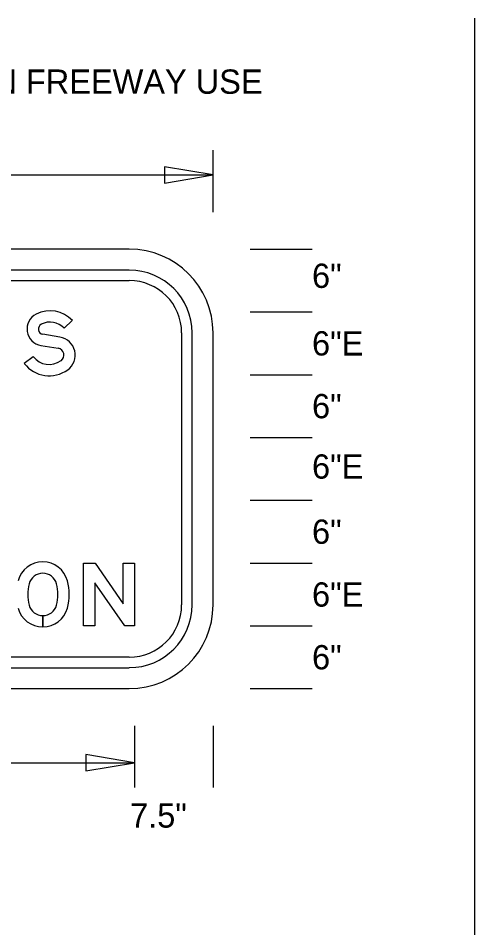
# Model space of a CAD drawing. Extents: x 0 to 770, y 0 to 495.
# Drawn here: x 319.6 to 385.3, y 363.9 to 495 of the extents above; entities that cross this region are included whole.
import ezdxf

# ---------------------------------------------------------------- set-up
doc = ezdxf.new("R2010")
doc.units = 0
for name, color, linetype in [('Dimension', 7, 'Continuous'), ('GSBWFill', 7, 'Continuous'), ('GSColorFill', 7, 'Continuous'), ('GSDims', 7, 'Continuous'), ('GSOutline', 7, 'Continuous'), ('SheetLines_dp', 7, 'Continuous'), ('TextStructures', 7, 'Continuous')]:
    doc.layers.add(name, color=color, linetype=linetype)

msp = doc.modelspace()

# ---------------------------------------------------------------- linework, layer by layer
at = {"layer": 'Dimension'}
for points in [[(347.62, 472.41), (340.61, 473.59), (340.61, 471.22)], [(336.32, 387.73), (329.3, 388.91), (329.3, 386.54)]]:
    msp.add_lwpolyline(points, close=True, dxfattribs=at)
at = {"layer": 'GSBWFill'}
for p, q in [((335.56, 461.72), (233.06, 461.72)), ((335.56, 458.71), (233.06, 458.71)), ((233.06, 457.2), (335.56, 457.2)), ((326.17, 450.33), (327.36, 451.43)), ((343.1, 449.66), (343.1, 410.47)), ((344.61, 410.47), (344.61, 449.66)), ((347.62, 410.47), (347.62, 449.66)), ((325.58, 449.05), (323.12, 449.46)), ((322.85, 447.86), (325.31, 447.44)), ((321.73, 446.23), (320.44, 445.24)), ((323.11, 407.3), (323.11, 408.92)), ((323.11, 408.92), (323.11, 407.3)), ((335.56, 402.93), (233.07, 402.93)), ((233.07, 401.42), (335.56, 401.42)), ((233.06, 398.41), (335.56, 398.41))]:
    msp.add_line(p, q, dxfattribs=at)
msp.add_lwpolyline([(336.32, 416.5), (336.32, 407.45), (334.92, 407.45), (330.62, 413.65), (330.62, 407.45), (328.99, 407.45), (328.99, 416.5), (330.63, 416.5), (334.69, 410.64), (334.69, 416.5)], close=True, dxfattribs=at)
for centre, radius, start, end in [((335.56, 449.66), 12.06, 0, 90), ((335.56, 449.66), 9.04, 0, 90), ((335.56, 449.66), 7.54, 0, 90), ((323.25, 450.22), 2.4, 116.9123, 260.4087), ((324.15, 448.45), 4.39, 42.8759, 116.9123), ((323.25, 450.22), 0.769, 116.9123, 260.4087), ((324.15, 448.45), 2.76, 42.8759, 116.9123), ((325.15, 446.46), 2.62, 306.123, 80.4087), ((325.15, 446.46), 0.995, 306.123, 80.4087), ((324.03, 448), 2.89, 217.5895, 306.123), ((324.03, 448), 4.52, 217.5895, 306.123), ((335.56, 410.47), 9.04, 270, 0), ((335.56, 410.47), 7.54, 270, 0), ((335.56, 410.47), 12.06, 270, 0)]:
    msp.add_arc(centre, radius, start, end, dxfattribs=at)
for centre, major_axis, start_param, end_param in [((323.11, 412.99), (0, 3.67), 4.973521, 7.592849), ((323.11, 412.99), (0, 2.04), 4.973521, 7.592849), ((326.91, 411.98), (0, 5.97), 1.309664, 1.831929), ((319.31, 411.98), (0, 5.97), 4.451257, 4.973521), ((319.31, 411.98), (0, 7.6), 4.451257, 4.973521), ((323.11, 410.96), (0, 2.04), 1.831929, 3.141593), ((323.11, 410.96), (0, 2.04), 3.141815, 4.451257), ((323.11, 410.96), (0, 3.67), 1.831929, 3.141593), ((323.11, 410.96), (0, 3.67), 3.141716, 4.451257)]:
    msp.add_ellipse(centre, major_axis=major_axis, ratio=0.999994, start_param=start_param, end_param=end_param, dxfattribs=at)
at = {"layer": 'GSColorFill'}
for p, q in [((326.17, 450.33), (327.36, 451.43)), ((325.58, 449.05), (323.12, 449.46)), ((322.85, 447.86), (325.31, 447.44)), ((321.73, 446.23), (320.44, 445.24)), ((323.11, 407.3), (323.11, 408.92)), ((323.11, 408.92), (323.11, 407.3))]:
    msp.add_line(p, q, dxfattribs=at)
msp.add_lwpolyline([(336.32, 416.5), (336.32, 407.45), (334.92, 407.45), (330.62, 413.65), (330.62, 407.45), (328.99, 407.45), (328.99, 416.5), (330.63, 416.5), (334.69, 410.64), (334.69, 416.5)], close=True, dxfattribs=at)
for centre, radius, start, end in [((323.25, 450.22), 2.4, 116.9123, 260.4087), ((324.15, 448.45), 4.39, 42.8759, 116.9123), ((323.25, 450.22), 0.769, 116.9123, 260.4087), ((324.15, 448.45), 2.76, 42.8759, 116.9123), ((325.15, 446.46), 2.62, 306.123, 80.4087), ((325.15, 446.46), 0.995, 306.123, 80.4087), ((324.03, 448), 2.89, 217.5895, 306.123), ((324.03, 448), 4.52, 217.5895, 306.123)]:
    msp.add_arc(centre, radius, start, end, dxfattribs=at)
for centre, major_axis, start_param, end_param in [((323.11, 412.99), (0, 3.67), 4.973521, 7.592849), ((323.11, 412.99), (0, 2.04), 4.973521, 7.592849), ((326.91, 411.98), (0, 5.97), 1.309664, 1.831929), ((319.31, 411.98), (0, 5.97), 4.451257, 4.973521), ((319.31, 411.98), (0, 7.6), 4.451257, 4.973521), ((323.11, 410.96), (0, 2.04), 1.831929, 3.141593), ((323.11, 410.96), (0, 2.04), 3.141815, 4.451257), ((323.11, 410.96), (0, 3.67), 1.831929, 3.141593), ((323.11, 410.96), (0, 3.67), 3.141716, 4.451257)]:
    msp.add_ellipse(centre, major_axis=major_axis, ratio=0.999994, start_param=start_param, end_param=end_param, dxfattribs=at)
at = {"layer": 'GSDims'}
for p, q in [((347.62, 467.06), (347.62, 475.97)), ((221, 472.41), (347.62, 472.41)), ((352.97, 461.72), (361.87, 461.72)), ((352.97, 452.68), (361.87, 452.68)), ((352.97, 452.68), (361.87, 452.68)), ((352.97, 443.63), (361.87, 443.63)), ((352.97, 443.63), (361.87, 443.63)), ((352.97, 434.59), (361.87, 434.59)), ((352.97, 434.59), (361.87, 434.59)), ((352.97, 425.54), (361.87, 425.54)), ((352.97, 425.54), (361.87, 425.54)), ((352.97, 416.5), (361.87, 416.5)), ((352.97, 416.5), (361.87, 416.5)), ((352.97, 407.45), (361.87, 407.45)), ((352.97, 407.45), (361.87, 407.45)), ((352.97, 398.41), (361.87, 398.41)), ((336.32, 393.07), (336.32, 384.16)), ((336.32, 393.07), (336.32, 384.16)), ((347.62, 393.07), (347.62, 384.16)), ((232.31, 387.73), (336.32, 387.73))]:
    msp.add_line(p, q, dxfattribs=at)
at = {"layer": 'GSOutline'}
for p, q in [((326.17, 450.33), (327.36, 451.43)), ((325.58, 449.05), (323.12, 449.46)), ((322.85, 447.86), (325.31, 447.44)), ((321.73, 446.23), (320.44, 445.24))]:
    msp.add_line(p, q, dxfattribs=at)
msp.add_lwpolyline([(336.32, 416.5), (336.32, 407.45), (334.92, 407.45), (330.62, 413.65), (330.62, 407.45), (328.99, 407.45), (328.99, 416.5), (330.63, 416.5), (334.69, 410.64), (334.69, 416.5)], close=True, dxfattribs=at)
for centre, radius, start, end in [((323.25, 450.22), 2.4, 116.9123, 260.4087), ((324.15, 448.45), 4.39, 42.8759, 116.9123), ((323.25, 450.22), 0.769, 116.9123, 260.4087), ((324.15, 448.45), 2.76, 42.8759, 116.9123), ((325.15, 446.46), 2.62, 306.123, 80.4087), ((325.15, 446.46), 0.995, 306.123, 80.4087), ((324.03, 448), 2.89, 217.5895, 306.123), ((324.03, 448), 4.52, 217.5895, 306.123)]:
    msp.add_arc(centre, radius, start, end, dxfattribs=at)
for centre, major_axis, start_param, end_param in [((323.11, 412.99), (0, 3.67), 4.973521, 7.592849), ((323.11, 412.99), (0, 2.04), 4.973521, 7.592849), ((326.91, 411.98), (0, 5.97), 1.309664, 1.831929), ((319.31, 411.98), (0, 5.97), 4.451257, 4.973521), ((319.31, 411.98), (0, 7.6), 4.451257, 4.973521), ((323.11, 410.96), (0, 2.04), 1.831929, 4.451257), ((323.11, 410.96), (0, 3.67), 1.831929, 4.451257)]:
    msp.add_ellipse(centre, major_axis=major_axis, ratio=0.999994, start_param=start_param, end_param=end_param, dxfattribs=at)
at = {"layer": 'SheetLines_dp'}
msp.add_line((385.3, 0), (385.3, 495), dxfattribs=at)

# ---------------------------------------------------------------- texts
at = {"layer": 'TextStructures'}
for s, p in [('OTHER THAN FREEWAY USE', (288.96, 484.11)), ('6"', (361.87, 456.14)), ('6"E', (361.87, 446.4)), ('6"', (361.87, 437.36)), ('6"E', (361.87, 428.66)), ('6"', (361.87, 419.27)), ('6"E', (361.87, 410.22)), ('6"', (361.87, 401.18)), ('7.5"', (335.68, 378.38))]:
    msp.add_text(s, height=3.5, dxfattribs=at).set_placement(p)

doc.saveas('drawing.dxf')
